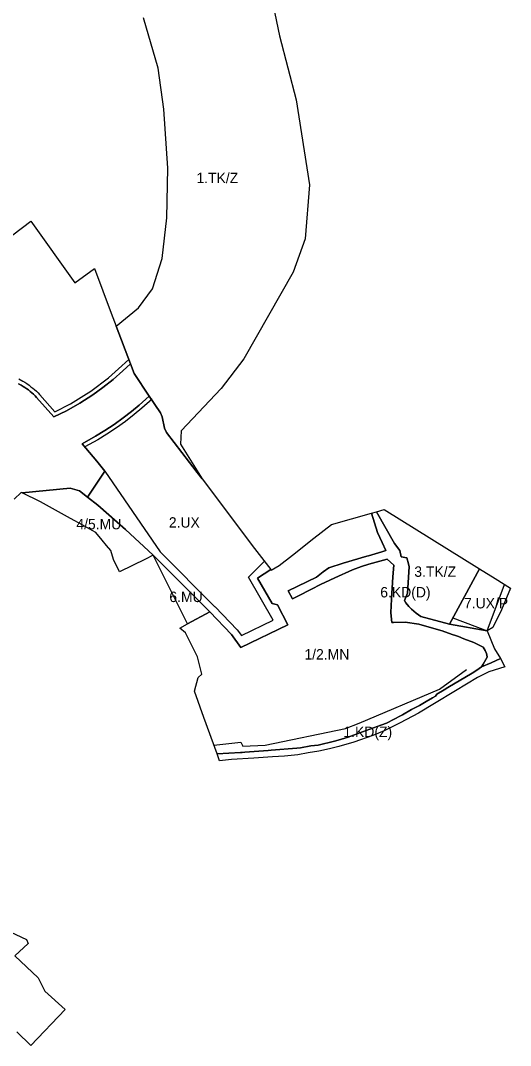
# Model space of a CAD drawing. Extents: x 7426363 to 7427567, y 5543397 to 5546605.
# Drawn here: x 7427055 to 7427526, y 5543397 to 5544381 of the extents above; entities that cross this region are included whole.
import ezdxf

# ---------------------------------------------------------------- set-up
doc = ezdxf.new("R2010")
doc.units = 0
for name, color, linetype in [('linie_rozgraniczajace', 7, 'Continuous'), ('linie_zabudowy_nieprzekraczalne', 7, 'Continuous'), ('oznaczenia_przeznaczen', 7, 'Continuous')]:
    doc.layers.add(name, color=color, linetype=linetype)

msp = doc.modelspace()

# ---------------------------------------------------------------- linework, layer by layer
at = {"layer": 'linie_rozgraniczajace'}
for points in [[(7427297.75, 5544395.41), (7427304.02, 5544366.49), (7427319.91, 5544304.89), (7427332.73, 5544223.38), (7427328.45, 5544171.48), (7427316.91, 5544139.47), (7427269.6, 5544056.14), (7427248, 5544027.54), (7427209.61, 5543986.89), (7427208.89, 5543974.1), (7427229.61, 5543940.85), (7427224.95, 5543946.91), (7427195.52, 5543985.21), (7427193.53, 5543989.56), (7427191.34, 5544000.43), (7427189.56, 5544004.34), (7427178.86, 5544020.35), (7427164.37, 5544042.02), (7427160.71, 5544051.48), (7427147.17, 5544087.5), (7427168.48, 5544105.02), (7427181.84, 5544123.27), (7427191.41, 5544152.36), (7427195.86, 5544191.61), (7427196.61, 5544239.27), (7427192.97, 5544295.9), (7427187.34, 5544335.36), (7427173.29, 5544383.64)], [(7426937.57, 5544091.78), (7427065.07, 5544188.4), (7427107.31, 5544129.13), (7427126.13, 5544142.93), (7427142.21, 5544099.88), (7427147.17, 5544087.5), (7427160.71, 5544051.48), (7427153.55, 5544044.6), (7427144.22, 5544036.4), (7427134.38, 5544028.55), (7427124.53, 5544021.45), (7427112.08, 5544013.43), (7427099.47, 5544006.28), (7427087.4, 5544000.28), (7427070.74, 5544018.97), (7427070.61, 5544019.11), (7427069.17, 5544020.64), (7427067.69, 5544022.12), (7427066.14, 5544023.54), (7427064.55, 5544024.9), (7427062.9, 5544026.2), (7427061.2, 5544027.43), (7427059.46, 5544028.6), (7427057.68, 5544029.7), (7427055.85, 5544030.73), (7427053.38, 5544032.02)], [(7427053.38, 5544032.02), (7427055.85, 5544030.73), (7427057.68, 5544029.7), (7427059.46, 5544028.6), (7427061.2, 5544027.43), (7427062.9, 5544026.2), (7427064.55, 5544024.9), (7427066.14, 5544023.54), (7427067.69, 5544022.12), (7427069.17, 5544020.64), (7427070.61, 5544019.11), (7427070.74, 5544018.97), (7427087.4, 5544000.28), (7427099.47, 5544006.28), (7427112.08, 5544013.43), (7427124.53, 5544021.45), (7427134.38, 5544028.55), (7427144.22, 5544036.4), (7427153.55, 5544044.6), (7427160.71, 5544051.48), (7427164.37, 5544042.02), (7427178.86, 5544020.35), (7427169.27, 5544011.74), (7427161.9, 5544005.65), (7427153.67, 5543999.3), (7427145.18, 5543993.17), (7427136.06, 5543987.13), (7427127.38, 5543981.8), (7427114.47, 5543974.63), (7427128.43, 5543957.68), (7427136.29, 5543948.14), (7427119.48, 5543923.3), (7427111.93, 5543929.24), (7427103.01, 5543931.83), (7427056.85, 5543927.29), (7427055.86, 5543927.77), (7427049.2, 5543921.17)], [(7427035.6, 5543510.17), (7427061.03, 5543498.44), (7427062.6, 5543494.63), (7427049.91, 5543482.52), (7427072.09, 5543461.55), (7427078.69, 5543448.78), (7427098.08, 5543431.18), (7427065.29, 5543396.54), (7427051.65, 5543409.65)]]:
    msp.add_lwpolyline(points, dxfattribs=at)
for points in [[(7427114.47, 5543974.63), (7427127.38, 5543981.8), (7427136.06, 5543987.13), (7427145.18, 5543993.17), (7427153.67, 5543999.3), (7427161.9, 5544005.65), (7427169.27, 5544011.74), (7427178.86, 5544020.35), (7427189.56, 5544004.34), (7427191.34, 5544000.43), (7427193.53, 5543989.56), (7427195.52, 5543985.21), (7427224.95, 5543946.91), (7427229.61, 5543940.85), (7427246.28, 5543918.82), (7427277.63, 5543876.77), (7427295.6, 5543853.61), (7427282.76, 5543845.48), (7427296.99, 5543821.17), (7427301.91, 5543819.84), (7427311.92, 5543800.53), (7427266.7, 5543778.96), (7427257.95, 5543791.41), (7427237.01, 5543813.11), (7427182.73, 5543867.51), (7427156.11, 5543892.11), (7427129.44, 5543915.45), (7427119.48, 5543923.3), (7427136.29, 5543948.14), (7427128.43, 5543957.68)], [(7427056.85, 5543927.29), (7427103.01, 5543931.83), (7427111.93, 5543929.24), (7427119.48, 5543923.3), (7427129.44, 5543915.45), (7427156.11, 5543892.11), (7427182.73, 5543867.51), (7427175.15, 5543863.76), (7427150.27, 5543851.45), (7427144.48, 5543863.32), (7427141.85, 5543872.01), (7427137.81, 5543876.93), (7427133.76, 5543881.85), (7427127.61, 5543889.33), (7427124.1, 5543891.26), (7427114.97, 5543896.3), (7427103.26, 5543902.76), (7427091.86, 5543909.05), (7427074.32, 5543918.72)], [(7427208.14, 5543797.47), (7427215.65, 5543801.67), (7427237.01, 5543813.11), (7427257.95, 5543791.41), (7427266.7, 5543778.96), (7427311.92, 5543800.53), (7427301.91, 5543819.84), (7427296.99, 5543821.17), (7427282.76, 5543845.48), (7427295.6, 5543853.61), (7427296.06, 5543853.02), (7427303.64, 5543857.72), (7427316.38, 5543867.68), (7427336.88, 5543884.01), (7427353.71, 5543897.14), (7427372.95, 5543902.57), (7427392.23, 5543907.86), (7427397.95, 5543889.36), (7427400.36, 5543884.65), (7427402.4, 5543879.7), (7427405.9, 5543872.11), (7427402.32, 5543870.63), (7427389.31, 5543866.87), (7427387.85, 5543866.63), (7427364.98, 5543859.78), (7427351.17, 5543855.34), (7427345.97, 5543851.37), (7427339.29, 5543846.28), (7427312.39, 5543833.32), (7427316.3, 5543825.63), (7427322.23, 5543828.63), (7427333.88, 5543834.53), (7427343.84, 5543839.61), (7427347.39, 5543841.17), (7427357.15, 5543845.78), (7427373.85, 5543853.52), (7427382.65, 5543856.72), (7427389.65, 5543858.82), (7427407.32, 5543863.72), (7427413.7, 5543857.93), (7427412.63, 5543846.69), (7427411.48, 5543825.38), (7427410.88, 5543812.51), (7427411.18, 5543808.95), (7427411.75, 5543802.83), (7427413.28, 5543802.97), (7427424.72, 5543803.26), (7427437.72, 5543801.26), (7427449.97, 5543797.82), (7427459.98, 5543794.97), (7427469.7, 5543791.41), (7427472.85, 5543790.26), (7427475.8, 5543789.31), (7427480.93, 5543787.09), (7427490.46, 5543783.63), (7427499.38, 5543779.04), (7427501.3, 5543775.84), (7427502.55, 5543772.97), (7427503.25, 5543770), (7427503.34, 5543769.6), (7427499.38, 5543762.86), (7427498.01, 5543760.15), (7427493.47, 5543757.15), (7427488.92, 5543754.15), (7427465.38, 5543740.38), (7427461.91, 5543738.16), (7427455.13, 5543733.89), (7427453.83, 5543732.11), (7427450.96, 5543730.49), (7427444.85, 5543726.9), (7427438.31, 5543723.16), (7427430.58, 5543719.16), (7427421.9, 5543714.01), (7427420.02, 5543713.05), (7427413.97, 5543709.95), (7427406.53, 5543706.18), (7427397.61, 5543702.85), (7427383.46, 5543697.76), (7427369.79, 5543692.84), (7427360.13, 5543689.71), (7427356.8, 5543688.81), (7427340.99, 5543684.9), (7427334.04, 5543684.3), (7427324.01, 5543682.62), (7427320.42, 5543682.16), (7427295.93, 5543680.26), (7427292.94, 5543680.01), (7427270.47, 5543678.28), (7427268.04, 5543678.14), (7427266.43, 5543678.07), (7427244.02, 5543676.73), (7427231.4, 5543711.6), (7427222.42, 5543736.87), (7427225.87, 5543750.08), (7427229.23, 5543753.09), (7427225.13, 5543769.94), (7427213.64, 5543792.81)], [(7427312.39, 5543833.32), (7427339.29, 5543846.28), (7427345.97, 5543851.37), (7427351.17, 5543855.34), (7427364.98, 5543859.78), (7427387.85, 5543866.63), (7427389.31, 5543866.87), (7427402.32, 5543870.63), (7427405.9, 5543872.11), (7427402.4, 5543879.7), (7427400.36, 5543884.65), (7427397.95, 5543889.36), (7427392.23, 5543907.86), (7427397.04, 5543909.19), (7427414.3, 5543878.61), (7427419.48, 5543872.14), (7427420.89, 5543865.79), (7427426.21, 5543865.12), (7427427.89, 5543859.27), (7427428.45, 5543856.2), (7427426.84, 5543830.99), (7427423.99, 5543824.15), (7427425.08, 5543821.87), (7427428.13, 5543818.07), (7427430.54, 5543815.68), (7427435.02, 5543811.82), (7427439.57, 5543808.51), (7427467.08, 5543801.18), (7427503.4, 5543794.81), (7427506.8, 5543786.25), (7427510.19, 5543777.68), (7427516, 5543768.14), (7427507.01, 5543764.15), (7427498.01, 5543760.15), (7427499.38, 5543762.86), (7427503.34, 5543769.6), (7427503.25, 5543770), (7427502.55, 5543772.97), (7427501.3, 5543775.84), (7427499.38, 5543779.04), (7427490.46, 5543783.63), (7427480.93, 5543787.09), (7427475.8, 5543789.31), (7427472.85, 5543790.26), (7427469.7, 5543791.41), (7427459.98, 5543794.97), (7427449.97, 5543797.82), (7427437.72, 5543801.26), (7427424.72, 5543803.26), (7427413.28, 5543802.97), (7427411.75, 5543802.83), (7427411.18, 5543808.95), (7427410.88, 5543812.51), (7427411.48, 5543825.38), (7427412.63, 5543846.69), (7427413.7, 5543857.93), (7427407.32, 5543863.72), (7427389.65, 5543858.82), (7427382.65, 5543856.72), (7427373.85, 5543853.52), (7427357.15, 5543845.78), (7427347.39, 5543841.17), (7427343.84, 5543839.61), (7427333.88, 5543834.53), (7427322.23, 5543828.63), (7427316.3, 5543825.63)], [(7427397.04, 5543909.19), (7427404.54, 5543911.33), (7427496.04, 5543854.46), (7427467.08, 5543801.18), (7427439.57, 5543808.51), (7427435.02, 5543811.82), (7427430.54, 5543815.68), (7427428.13, 5543818.07), (7427425.08, 5543821.87), (7427423.99, 5543824.15), (7427426.84, 5543830.99), (7427428.45, 5543856.2), (7427427.89, 5543859.27), (7427426.21, 5543865.12), (7427420.89, 5543865.79), (7427419.48, 5543872.14), (7427414.3, 5543878.61)], [(7427182.73, 5543867.51), (7427237.01, 5543813.11), (7427215.65, 5543801.67)], [(7427467.08, 5543801.18), (7427496.04, 5543854.46), (7427510.87, 5543845.08), (7427525.7, 5543835.69), (7427517.04, 5543814.93), (7427508.66, 5543798.05), (7427503.4, 5543794.81)], [(7427244.02, 5543676.73), (7427266.43, 5543678.07), (7427268.04, 5543678.14), (7427270.47, 5543678.28), (7427292.94, 5543680.01), (7427295.93, 5543680.26), (7427320.42, 5543682.16), (7427324.01, 5543682.62), (7427334.04, 5543684.3), (7427340.99, 5543684.9), (7427356.8, 5543688.81), (7427360.13, 5543689.71), (7427369.79, 5543692.84), (7427383.46, 5543697.76), (7427397.61, 5543702.85), (7427406.53, 5543706.18), (7427413.97, 5543709.95), (7427420.02, 5543713.05), (7427421.9, 5543714.01), (7427430.58, 5543719.16), (7427438.31, 5543723.16), (7427444.85, 5543726.9), (7427450.96, 5543730.49), (7427453.83, 5543732.11), (7427455.13, 5543733.89), (7427461.91, 5543738.16), (7427465.38, 5543740.38), (7427488.92, 5543754.15), (7427493.47, 5543757.15), (7427498.01, 5543760.15), (7427507.01, 5543764.15), (7427516, 5543768.14), (7427520.2, 5543760.38), (7427504.96, 5543755.49), (7427494.07, 5543750.01), (7427472.86, 5543737.2), (7427452.8, 5543725.14), (7427437.51, 5543715.87), (7427419.74, 5543706.42), (7427404.41, 5543698.89), (7427393.67, 5543694.38), (7427375.27, 5543687.76), (7427360.9, 5543683.68), (7427351.94, 5543681.58), (7427341.76, 5543679.29), (7427331.5, 5543677.52), (7427321.36, 5543675.88), (7427308.56, 5543674.58), (7427297.35, 5543673.74), (7427279.3, 5543672.68), (7427257.72, 5543671.29), (7427246.39, 5543670.12)]]:
    msp.add_lwpolyline(points, close=True, dxfattribs=at)
at = {"layer": 'linie_zabudowy_nieprzekraczalne'}
for points in [[(7427088.35, 5544005.23), (7427103.25, 5544013.03), (7427116.15, 5544020.81), (7427122.63, 5544025.01), (7427139.86, 5544038.03), (7427149.21, 5544046.4), (7427159.15, 5544055.52)], [(7427053.68, 5544036.81), (7427057.52, 5544034.74), (7427059.3, 5544033.71), (7427061.33, 5544032.32), (7427063.49, 5544030.71), (7427065.31, 5544029.39), (7427067.08, 5544027.99), (7427068.79, 5544026.54), (7427070.45, 5544025.01), (7427072.05, 5544023.43), (7427073.56, 5544021.81), (7427073.72, 5544021.63), (7427073.72, 5544021.63), (7427088.35, 5544005.23)], [(7427181.53, 5544017.37), (7427171.88, 5544008.71), (7427164.4, 5544002.53), (7427156.07, 5543996.09), (7427147.45, 5543989.88), (7427138.21, 5543983.76), (7427129.4, 5543978.35), (7427117.06, 5543971.49)], [(7427136.29, 5543948.14), (7427189.37, 5543870.77)], [(7427189.37, 5543870.77), (7427241.96, 5543818.06)], [(7427274.1, 5543846.5), (7427289.49, 5543861.64)], [(7427297.99, 5543804.96), (7427274.1, 5543846.5)], [(7427470.42, 5543807.33), (7427503.4, 5543794.81), (7427519.84, 5543839.4)], [(7427242.04, 5543817.97), (7427263.37, 5543795.88), (7427267.28, 5543790.32)], [(7427267.28, 5543790.32), (7427297.99, 5543804.96)], [(7427241.01, 5543685.06), (7427266.89, 5543687.99), (7427268.56, 5543683.97), (7427290.09, 5543684.94), (7427367.3, 5543701.07), (7427380.53, 5543706.03), (7427457.57, 5543738.74), (7427483.37, 5543757.62)]]:
    msp.add_lwpolyline(points, dxfattribs=at)

# ---------------------------------------------------------------- texts
at = {"layer": 'oznaczenia_przeznaczen'}
for s, p in [('1.TK/Z', (7427224.17, 5544224.9)), ('4/5.MU', (7427108.87, 5543892.4)), ('2.UX', (7427197.67, 5543893.99)), ('3.TK/Z', (7427433.36, 5543846.73)), ('6.MU', (7427198.18, 5543822.49)), ('6.KD(D)', (7427400.68, 5543826.96)), ('7.UX/P', (7427481.08, 5543816.41)), ('1/2.MN', (7427327.86, 5543767.28)), ('1.KD(Z)', (7427365.29, 5543692.84))]:
    msp.add_text(s, height=10, dxfattribs=at).set_placement(p)

doc.saveas('drawing.dxf')
